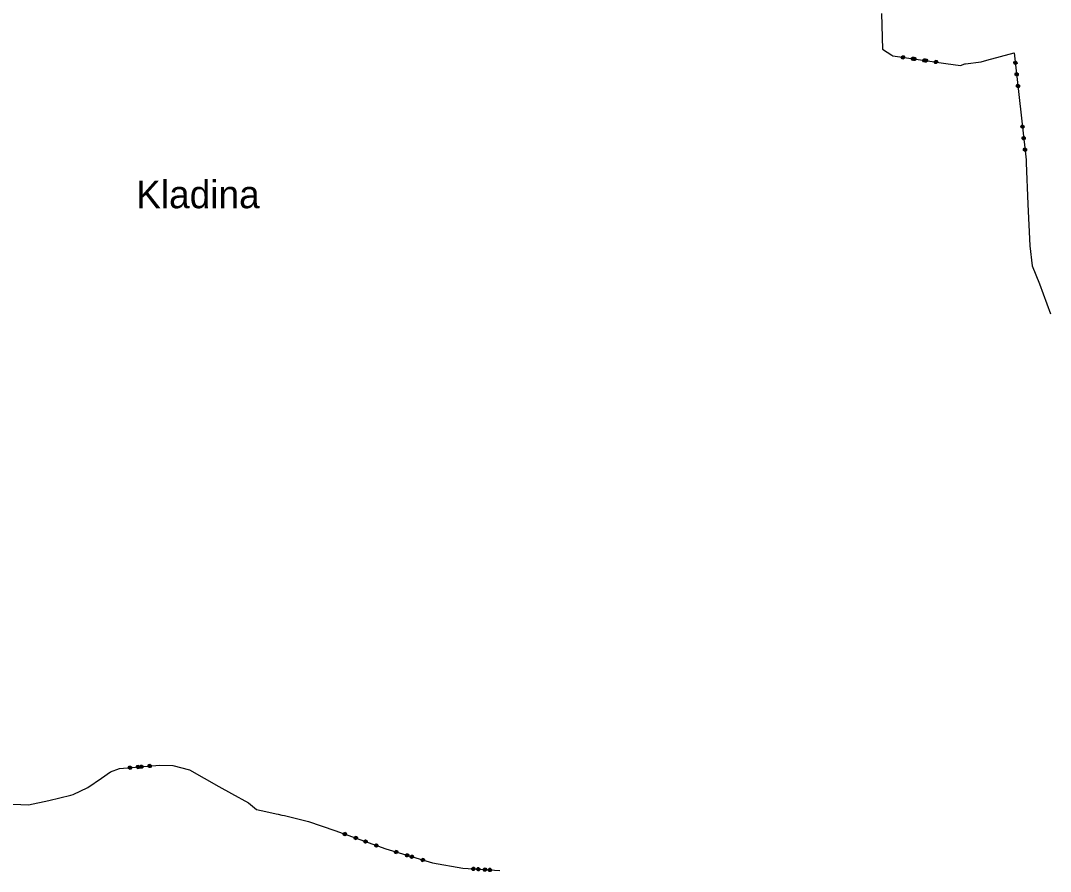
# Model space of a CAD drawing. Extents: x -643242 to -638517, y -1061413 to -1055378.
# Drawn here: x -640190 to -638851, y -1059652 to -1058546 of the extents above; entities that cross this region are included whole.
import ezdxf

# ---------------------------------------------------------------- set-up
doc = ezdxf.new("R2010")
doc.units = 0
for name, color, linetype in [('HRA_KU', 7, 'Continuous'), ('HRA_OB', 7, 'Continuous'), ('KU_OST', 7, 'Continuous')]:
    doc.layers.add(name, color=color, linetype=linetype)

msp = doc.modelspace()

# ---------------------------------------------------------------- linework, layer by layer
at = {"layer": 'HRA_KU'}
for points in [[(-640209.9, -1059564.5), (-640179.7, -1059565.8), (-640153.2, -1059559.8), (-640124.5, -1059553.2), (-640121.7, -1059552), (-640102.4, -1059543.3), (-640084.6, -1059530.9), (-640073, -1059522.7), (-640061.3, -1059518.6), (-640009, -1059513.9), (-639992, -1059514.3), (-639970.1, -1059520.2), (-639932.1, -1059541.8), (-639915.8, -1059551.1), (-639893.8, -1059563.2), (-639883.3, -1059571.5), (-639871.2, -1059574.2), (-639857.5, -1059577.3), (-639854.9, -1059577.9), (-639850.2, -1059578.9), (-639846.6, -1059579.7), (-639815.7, -1059587.2), (-639781.2, -1059598.9), (-639715, -1059623), (-639654.4, -1059641.2), (-639615, -1059648.1), (-639566.7, -1059650.9)], [(-640047, -1059515.4), (-640045.8, -1059516.4), (-640045.6, -1059518), (-640046.7, -1059519.3), (-640048.3, -1059519.4), (-640049.5, -1059518.4), (-640049.6, -1059516.8), (-640048.6, -1059515.5), (-640047, -1059515.4), (-640047, -1059515.6), (-640048.5, -1059515.8), (-640048.9, -1059516.3), (-640046.5, -1059516.1), (-640046, -1059516.5), (-640049.3, -1059516.8), (-640049.3, -1059517.3), (-640046, -1059517), (-640045.9, -1059517.5), (-640049.3, -1059517.8), (-640049.2, -1059518.2), (-640045.9, -1059517.9), (-640046.3, -1059518.5), (-640048.7, -1059518.7), (-640048.2, -1059519.1), (-640046.7, -1059519)], [(-640036.4, -1059514.4), (-640035.2, -1059515.5), (-640035.1, -1059517.1), (-640036.1, -1059518.3), (-640037.7, -1059518.5), (-640038.9, -1059517.4), (-640039.1, -1059515.8), (-640038.1, -1059514.6), (-640036.4, -1059514.4), (-640036.5, -1059514.7), (-640037.9, -1059514.8), (-640038.3, -1059515.3), (-640036, -1059515.1), (-640035.4, -1059515.5), (-640038.8, -1059515.8), (-640038.7, -1059516.3), (-640035.4, -1059516), (-640035.3, -1059516.5), (-640038.7, -1059516.8), (-640038.7, -1059517.3), (-640035.3, -1059517), (-640035.7, -1059517.5), (-640038.1, -1059517.7), (-640037.6, -1059518.2), (-640036.2, -1059518)], [(-640032.1, -1059514), (-640030.8, -1059515.1), (-640030.7, -1059516.7), (-640031.7, -1059517.9), (-640033.3, -1059518.1), (-640034.6, -1059517), (-640034.7, -1059515.4), (-640033.7, -1059514.2), (-640032.1, -1059514), (-640032.2, -1059514.3), (-640033.7, -1059514.4), (-640034.1, -1059514.9), (-640031.7, -1059514.7), (-640031.2, -1059515.2), (-640034.5, -1059515.5), (-640034.5, -1059515.9), (-640031.1, -1059515.6), (-640031.1, -1059516.1), (-640034.4, -1059516.4), (-640034.4, -1059516.9), (-640031.1, -1059516.6), (-640031.5, -1059517.1), (-640033.9, -1059517.3), (-640033.4, -1059517.8), (-640031.9, -1059517.6)], [(-640021.5, -1059513.1), (-640020.3, -1059514.1), (-640020.1, -1059515.7), (-640021.1, -1059517), (-640022.8, -1059517.1), (-640024, -1059516.1), (-640024.1, -1059514.5), (-640023.1, -1059513.2), (-640021.5, -1059513.1), (-640021.7, -1059513.3), (-640023.1, -1059513.5), (-640023.5, -1059514), (-640021.1, -1059513.8), (-640020.6, -1059514.2), (-640024, -1059514.5), (-640023.9, -1059515), (-640020.6, -1059514.7), (-640020.5, -1059515.1), (-640023.9, -1059515.5), (-640023.8, -1059515.9), (-640020.5, -1059515.6), (-640020.9, -1059516.1), (-640023.3, -1059516.4), (-640022.8, -1059516.8), (-640021.4, -1059516.7)], [(-639766.8, -1059602.1), (-639766.2, -1059603.6), (-639766.7, -1059605.1), (-639768.2, -1059605.8), (-639769.7, -1059605.2), (-639770.4, -1059603.8), (-639769.8, -1059602.2), (-639768.4, -1059601.6), (-639766.8, -1059602.1), (-639767, -1059602.3), (-639768.3, -1059601.8), (-639768.9, -1059602.1), (-639766.7, -1059602.9), (-639766.4, -1059603.5), (-639769.6, -1059602.4), (-639769.7, -1059602.8), (-639766.6, -1059604), (-639766.7, -1059604.4), (-639769.9, -1059603.3), (-639770.1, -1059603.7), (-639766.9, -1059604.9), (-639767.5, -1059605.2), (-639769.8, -1059604.4), (-639769.5, -1059605), (-639768.1, -1059605.5)], [(-639752.7, -1059607.2), (-639752.1, -1059608.7), (-639752.6, -1059610.2), (-639754.1, -1059610.9), (-639755.6, -1059610.3), (-639756.3, -1059608.9), (-639755.7, -1059607.4), (-639754.3, -1059606.7), (-639752.7, -1059607.2), (-639753, -1059607.4), (-639754.3, -1059606.9), (-639755, -1059607.2), (-639752.7, -1059608), (-639752.4, -1059608.6), (-639755.6, -1059607.5), (-639755.7, -1059607.9), (-639752.6, -1059609.1), (-639752.7, -1059609.5), (-639755.9, -1059608.4), (-639756.1, -1059608.8), (-639752.9, -1059610), (-639753.5, -1059610.3), (-639755.8, -1059609.4), (-639755.5, -1059610.1), (-639754.1, -1059610.5)], [(-639740.1, -1059611.8), (-639739.4, -1059613.3), (-639739.9, -1059614.8), (-639741.4, -1059615.5), (-639742.9, -1059614.9), (-639743.6, -1059613.5), (-639743.1, -1059612), (-639741.6, -1059611.3), (-639740.1, -1059611.8), (-639740.2, -1059612), (-639741.6, -1059611.5), (-639742.2, -1059611.8), (-639739.9, -1059612.7), (-639739.6, -1059613.3), (-639742.8, -1059612.1), (-639743, -1059612.6), (-639739.8, -1059613.7), (-639740, -1059614.2), (-639743.1, -1059613), (-639743.3, -1059613.5), (-639740.1, -1059614.6), (-639740.7, -1059614.9), (-639743, -1059614.1), (-639742.7, -1059614.7), (-639741.4, -1059615.2)], [(-639726, -1059617), (-639725.3, -1059618.4), (-639725.8, -1059619.9), (-639727.3, -1059620.6), (-639728.8, -1059620.1), (-639729.5, -1059618.6), (-639729, -1059617.1), (-639727.5, -1059616.4), (-639726, -1059617), (-639726.2, -1059617.1), (-639727.6, -1059616.6), (-639728.2, -1059616.9), (-639725.9, -1059617.7), (-639725.7, -1059618.3), (-639728.8, -1059617.2), (-639729, -1059617.6), (-639725.8, -1059618.8), (-639726, -1059619.2), (-639729.1, -1059618.1), (-639729.3, -1059618.6), (-639726.1, -1059619.7), (-639726.8, -1059620), (-639729, -1059619.2), (-639728.7, -1059619.8), (-639727.4, -1059620.3)], [(-639700.4, -1059625.4), (-639699.7, -1059626.8), (-639700.1, -1059628.3), (-639701.6, -1059629.1), (-639703.1, -1059628.6), (-639703.9, -1059627.2), (-639703.4, -1059625.7), (-639702, -1059624.9), (-639700.4, -1059625.4), (-639700.6, -1059625.6), (-639701.9, -1059625.2), (-639702.5, -1059625.5), (-639700.2, -1059626.2), (-639699.9, -1059626.8), (-639703.1, -1059625.8), (-639703.3, -1059626.3), (-639700.1, -1059627.2), (-639700.2, -1059627.7), (-639703.4, -1059626.7), (-639703.6, -1059627.2), (-639700.3, -1059628.1), (-639700.9, -1059628.5), (-639703.2, -1059627.8), (-639702.9, -1059628.4), (-639701.5, -1059628.8)], [(-639686.1, -1059629.7), (-639685.3, -1059631.1), (-639685.8, -1059632.6), (-639687.2, -1059633.4), (-639688.8, -1059632.9), (-639689.5, -1059631.5), (-639689, -1059630), (-639687.6, -1059629.2), (-639686.1, -1059629.7), (-639686.3, -1059629.9), (-639687.7, -1059629.4), (-639688.3, -1059629.8), (-639686, -1059630.5), (-639685.7, -1059631), (-639688.9, -1059630.1), (-639689, -1059630.5), (-639685.8, -1059631.5), (-639686, -1059632), (-639689.2, -1059631), (-639689.3, -1059631.5), (-639686.1, -1059632.4), (-639686.7, -1059632.7), (-639689, -1059632.1), (-639688.7, -1059632.7), (-639687.3, -1059633.1)], [(-639680.1, -1059631.5), (-639679.3, -1059632.9), (-639679.8, -1059634.4), (-639681.2, -1059635.2), (-639682.8, -1059634.7), (-639683.5, -1059633.3), (-639683, -1059631.8), (-639681.6, -1059631), (-639680.1, -1059631.5), (-639680.2, -1059631.7), (-639681.6, -1059631.3), (-639682.2, -1059631.6), (-639679.9, -1059632.3), (-639679.6, -1059632.9), (-639682.8, -1059631.9), (-639682.9, -1059632.4), (-639679.7, -1059633.3), (-639679.8, -1059633.8), (-639683.1, -1059632.8), (-639683.2, -1059633.3), (-639680, -1059634.3), (-639680.6, -1059634.6), (-639682.9, -1059633.9), (-639682.6, -1059634.5), (-639681.2, -1059634.9)], [(-639665.7, -1059635.8), (-639664.9, -1059637.2), (-639665.4, -1059638.8), (-639666.8, -1059639.5), (-639668.4, -1059639.1), (-639669.2, -1059637.6), (-639668.7, -1059636.1), (-639667.3, -1059635.3), (-639665.7, -1059635.8), (-639666, -1059636), (-639667.3, -1059635.6), (-639667.9, -1059635.9), (-639665.6, -1059636.6), (-639665.3, -1059637.2), (-639668.5, -1059636.2), (-639668.7, -1059636.7), (-639665.4, -1059637.6), (-639665.6, -1059638.1), (-639668.8, -1059637.1), (-639668.9, -1059637.6), (-639665.7, -1059638.5), (-639666.3, -1059638.9), (-639668.6, -1059638.2), (-639668.3, -1059638.8), (-639666.9, -1059639.2)], [(-639600.3, -1059647.1), (-639599.2, -1059648.3), (-639599.3, -1059649.9), (-639600.5, -1059651), (-639602.1, -1059650.9), (-639603.2, -1059649.7), (-639603.1, -1059648), (-639601.9, -1059647), (-639600.3, -1059647.1), (-639600.4, -1059647.3), (-639601.8, -1059647.2), (-639602.3, -1059647.7), (-639599.9, -1059647.8), (-639599.5, -1059648.3), (-639602.8, -1059648.1), (-639602.9, -1059648.6), (-639599.5, -1059648.8), (-639599.5, -1059649.3), (-639602.9, -1059649.1), (-639602.9, -1059649.6), (-639599.6, -1059649.8), (-639600.1, -1059650.2), (-639602.5, -1059650.1), (-639602, -1059650.6), (-639600.6, -1059650.7)], [(-639594, -1059647.4), (-639592.9, -1059648.6), (-639593, -1059650.3), (-639594.2, -1059651.3), (-639595.8, -1059651.2), (-639596.9, -1059650), (-639596.8, -1059648.4), (-639595.6, -1059647.3), (-639594, -1059647.4), (-639594, -1059647.7), (-639595.5, -1059647.6), (-639596, -1059648), (-639593.6, -1059648.2), (-639593.1, -1059648.7), (-639596.5, -1059648.5), (-639596.5, -1059649), (-639593.2, -1059649.2), (-639593.2, -1059649.6), (-639596.5, -1059649.4), (-639596.6, -1059649.9), (-639593.2, -1059650.1), (-639593.7, -1059650.6), (-639596.1, -1059650.4), (-639595.7, -1059650.9), (-639594.2, -1059651)], [(-639585.3, -1059647.9), (-639584.3, -1059649.1), (-639584.3, -1059650.7), (-639585.6, -1059651.8), (-639587.2, -1059651.7), (-639588.2, -1059650.5), (-639588.1, -1059648.9), (-639586.9, -1059647.8), (-639585.3, -1059647.9), (-639585.5, -1059648.2), (-639587, -1059648.1), (-639587.5, -1059648.5), (-639585.1, -1059648.7), (-639584.6, -1059649.2), (-639588, -1059649), (-639588, -1059649.5), (-639584.6, -1059649.6), (-639584.7, -1059650.1), (-639588, -1059649.9), (-639588.1, -1059650.4), (-639584.7, -1059650.6), (-639585.2, -1059651.1), (-639587.6, -1059650.9), (-639587.2, -1059651.4), (-639585.7, -1059651.5)], [(-639579, -1059648.3), (-639577.9, -1059649.5), (-639578, -1059651.1), (-639579.2, -1059652.2), (-639580.8, -1059652.1), (-639581.9, -1059650.9), (-639581.8, -1059649.3), (-639580.6, -1059648.2), (-639579, -1059648.3), (-639579.2, -1059648.5), (-639580.6, -1059648.4), (-639581.1, -1059648.9), (-639578.7, -1059649), (-639578.3, -1059649.5), (-639581.6, -1059649.3), (-639581.7, -1059649.8), (-639578.3, -1059650), (-639578.3, -1059650.5), (-639581.7, -1059650.3), (-639581.7, -1059650.8), (-639578.4, -1059651), (-639578.9, -1059651.4), (-639581.3, -1059651.3), (-639580.8, -1059651.8), (-639579.4, -1059651.9)]]:
    msp.add_lwpolyline(points, dxfattribs=at)
at = {"layer": 'HRA_OB'}
for points in [[(-639070.8, -1058536.9), (-639069.7, -1058583.2), (-639057.6, -1058590.9), (-639056, -1058591.9), (-638987.1, -1058601.8), (-638968, -1058604.5), (-638962.5, -1058602.4), (-638961.7, -1058602.1), (-638941.3, -1058599.6), (-638933.8, -1058597.6), (-638898.2, -1058588), (-638882.9, -1058726.9), (-638882.8, -1058729.7), (-638882.7, -1058730.8), (-638880.8, -1058784.8), (-638878.1, -1058839.1), (-638875.1, -1058864.9), (-638865.6, -1058888.1), (-638851.3, -1058927.5)], [(-639041.9, -1058592), (-639040.9, -1058593.3), (-639041.1, -1058594.9), (-639042.4, -1058595.9), (-639044, -1058595.6), (-639045, -1058594.4), (-639044.8, -1058592.8), (-639043.5, -1058591.8), (-639041.9, -1058592), (-639041.8, -1058592.3), (-639043.3, -1058592.1), (-639043.8, -1058592.5), (-639041.4, -1058592.8), (-639041.1, -1058593.3), (-639044.3, -1058592.9), (-639044.4, -1058593.3), (-639041.3, -1058593.8), (-639041.3, -1058594.3), (-639044.4, -1058593.8), (-639044.5, -1058594.3), (-639041.3, -1058594.8), (-639041.7, -1058595.2), (-639044.3, -1058594.8), (-639043.9, -1058595.4), (-639042.2, -1058595.6)], [(-639028.8, -1058593.9), (-639027.9, -1058595.2), (-639028.1, -1058596.8), (-639029.4, -1058597.7), (-639031, -1058597.5), (-639031.9, -1058596.2), (-639031.7, -1058594.6), (-639030.4, -1058593.6), (-639028.8, -1058593.9), (-639028.8, -1058594.1), (-639030.2, -1058593.9), (-639030.8, -1058594.3), (-639028.4, -1058594.7), (-639028.1, -1058595.2), (-639031.3, -1058594.7), (-639031.4, -1058595.2), (-639028.2, -1058595.7), (-639028.2, -1058596.1), (-639031.4, -1058595.7), (-639031.5, -1058596.2), (-639028.3, -1058596.6), (-639028.7, -1058597), (-639031.2, -1058596.7), (-639030.9, -1058597.2), (-639029.2, -1058597.5)], [(-639026.9, -1058594.1), (-639026, -1058595.4), (-639026.2, -1058597), (-639027.5, -1058598), (-639029.1, -1058597.8), (-639030.1, -1058596.5), (-639029.8, -1058594.9), (-639028.6, -1058593.9), (-639026.9, -1058594.1), (-639027, -1058594.4), (-639028.5, -1058594.2), (-639029, -1058594.6), (-639026.6, -1058594.9), (-639026.2, -1058595.4), (-639029.6, -1058595), (-639029.6, -1058595.5), (-639026.3, -1058595.9), (-639026.4, -1058596.4), (-639029.7, -1058595.9), (-639029.8, -1058596.4), (-639026.4, -1058596.9), (-639027, -1058597.3), (-639029.3, -1058596.9), (-639028.9, -1058597.5), (-639027.5, -1058597.7)], [(-639013.9, -1058596), (-639012.9, -1058597.3), (-639013.2, -1058598.9), (-639014.5, -1058599.9), (-639016.1, -1058599.6), (-639017, -1058598.3), (-639016.8, -1058596.7), (-639015.5, -1058595.8), (-639013.9, -1058596), (-639014, -1058596.2), (-639015.4, -1058596), (-639016, -1058596.4), (-639013.6, -1058596.8), (-639013.2, -1058597.3), (-639016.5, -1058596.8), (-639016.6, -1058597.3), (-639013.3, -1058597.8), (-639013.3, -1058598.3), (-639016.7, -1058597.8), (-639016.7, -1058598.3), (-639013.4, -1058598.7), (-639013.9, -1058599.1), (-639016.3, -1058598.8), (-639015.9, -1058599.3), (-639014.5, -1058599.5)], [(-639012, -1058596.3), (-639011.1, -1058597.5), (-639011.3, -1058599.1), (-639012.6, -1058600.1), (-639014.2, -1058599.9), (-639015.2, -1058598.6), (-639014.9, -1058597), (-639013.6, -1058596), (-639012, -1058596.3), (-639012.3, -1058596.5), (-639013.7, -1058596.3), (-639014.2, -1058596.7), (-639011.9, -1058597), (-639011.5, -1058597.5), (-639014.6, -1058597.1), (-639014.7, -1058597.6), (-639011.6, -1058598), (-639011.6, -1058598.5), (-639014.7, -1058598.1), (-639014.8, -1058598.5), (-639011.8, -1058599), (-639012.1, -1058599.4), (-639014.5, -1058599.1), (-639014.3, -1058599.6), (-639012.8, -1058599.8)], [(-638999, -1058598.1), (-638998, -1058599.4), (-638998.3, -1058601), (-638999.6, -1058602), (-639001.2, -1058601.7), (-639002.1, -1058600.5), (-639001.9, -1058598.9), (-639000.6, -1058597.9), (-638999, -1058598.1), (-638999.3, -1058598.3), (-639000.7, -1058598.1), (-639001.1, -1058598.5), (-638998.9, -1058598.9), (-638998.5, -1058599.4), (-639001.6, -1058599), (-639001.6, -1058599.4), (-638998.5, -1058599.9), (-638998.6, -1058600.3), (-639001.7, -1058599.9), (-639001.8, -1058600.4), (-638998.7, -1058600.8), (-638999, -1058601.3), (-639001.5, -1058600.9), (-639001.2, -1058601.4), (-638999.8, -1058601.6)], [(-638894.7, -1058601.7), (-638895.7, -1058602.9), (-638897.3, -1058603.1), (-638898.6, -1058602.1), (-638898.8, -1058600.5), (-638897.8, -1058599.2), (-638896.2, -1058599), (-638894.9, -1058600.1), (-638894.7, -1058601.7), (-638895, -1058601.8), (-638895.1, -1058600.3), (-638895.6, -1058599.9), (-638895.4, -1058602.3), (-638895.8, -1058602.7), (-638896.2, -1058599.5), (-638896.6, -1058599.5), (-638896.3, -1058602.7), (-638896.8, -1058602.8), (-638897.1, -1058599.6), (-638897.6, -1058599.7), (-638897.2, -1058602.8), (-638897.8, -1058602.6), (-638898, -1058600), (-638898.5, -1058600.5), (-638898.3, -1058602.2)], [(-638893.1, -1058616.6), (-638894.1, -1058617.9), (-638895.7, -1058618.1), (-638897, -1058617.1), (-638897.1, -1058615.5), (-638896.1, -1058614.2), (-638894.5, -1058614), (-638893.3, -1058615), (-638893.1, -1058616.6), (-638893.3, -1058616.6), (-638893.5, -1058615.2), (-638894, -1058614.7), (-638893.7, -1058617.1), (-638894.2, -1058617.7), (-638894.5, -1058614.3), (-638895, -1058614.4), (-638894.6, -1058617.7), (-638895.1, -1058617.8), (-638895.5, -1058614.4), (-638896, -1058614.5), (-638895.6, -1058617.8), (-638896.1, -1058617.4), (-638896.4, -1058615), (-638896.8, -1058615.5), (-638896.7, -1058617)], [(-638891.4, -1058631.6), (-638892.4, -1058632.9), (-638894, -1058633), (-638895.3, -1058632), (-638895.5, -1058630.4), (-638894.5, -1058629.2), (-638892.9, -1058629), (-638891.6, -1058630), (-638891.4, -1058631.6), (-638891.7, -1058631.4), (-638891.8, -1058630), (-638892.4, -1058629.7), (-638892.1, -1058631.9), (-638892.5, -1058632.5), (-638892.9, -1058629.4), (-638893.4, -1058629.4), (-638893, -1058632.5), (-638893.5, -1058632.6), (-638893.8, -1058629.5), (-638894.3, -1058629.4), (-638894, -1058632.6), (-638894.5, -1058632.4), (-638894.8, -1058629.9), (-638895.2, -1058630.3), (-638895, -1058631.7)], [(-638885.6, -1058684.5), (-638886.6, -1058685.8), (-638888.2, -1058685.9), (-638889.5, -1058684.9), (-638889.7, -1058683.3), (-638888.6, -1058682.1), (-638887, -1058681.9), (-638885.8, -1058682.9), (-638885.6, -1058684.5), (-638885.8, -1058684.6), (-638886, -1058683.2), (-638886.5, -1058682.7), (-638886.3, -1058685.1), (-638886.7, -1058685.5), (-638887.1, -1058682.3), (-638887.5, -1058682.4), (-638887.2, -1058685.5), (-638887.7, -1058685.6), (-638888, -1058682.5), (-638888.5, -1058682.5), (-638888.1, -1058685.7), (-638888.6, -1058685.5), (-638888.9, -1058682.9), (-638889.4, -1058683.4), (-638889.2, -1058685)], [(-638884, -1058699.5), (-638885, -1058700.7), (-638886.6, -1058700.9), (-638887.8, -1058699.9), (-638888, -1058698.3), (-638887, -1058697), (-638885.4, -1058696.9), (-638884.1, -1058697.9), (-638884, -1058699.5), (-638884.2, -1058699.5), (-638884.4, -1058698), (-638884.9, -1058697.6), (-638884.6, -1058700), (-638885, -1058700.5), (-638885.4, -1058697.2), (-638885.9, -1058697.2), (-638885.5, -1058700.6), (-638886, -1058700.6), (-638886.4, -1058697.3), (-638886.8, -1058697.3), (-638886.5, -1058700.7), (-638887, -1058700.2), (-638887.3, -1058697.9), (-638887.7, -1058698.4), (-638887.5, -1058699.8)], [(-638882.3, -1058714.5), (-638883.3, -1058715.7), (-638884.9, -1058715.9), (-638886.2, -1058714.9), (-638886.4, -1058713.3), (-638885.4, -1058712), (-638883.7, -1058711.8), (-638882.5, -1058712.8), (-638882.3, -1058714.5), (-638882.6, -1058714.2), (-638882.7, -1058712.8), (-638883.2, -1058712.5), (-638883, -1058714.8), (-638883.4, -1058715.3), (-638883.8, -1058712.2), (-638884.2, -1058712.3), (-638883.9, -1058715.4), (-638884.4, -1058715.4), (-638884.7, -1058712.3), (-638885.2, -1058712.3), (-638884.9, -1058715.4), (-638885.4, -1058715.2), (-638885.6, -1058712.8), (-638886.1, -1058713.1), (-638885.9, -1058714.5)]]:
    msp.add_lwpolyline(points, dxfattribs=at)

# ---------------------------------------------------------------- texts
at = {"layer": 'KU_OST'}
msp.add_text('Kladina', height=36, dxfattribs=at).set_placement((-640039.6, -1058790))

doc.saveas('drawing.dxf')
